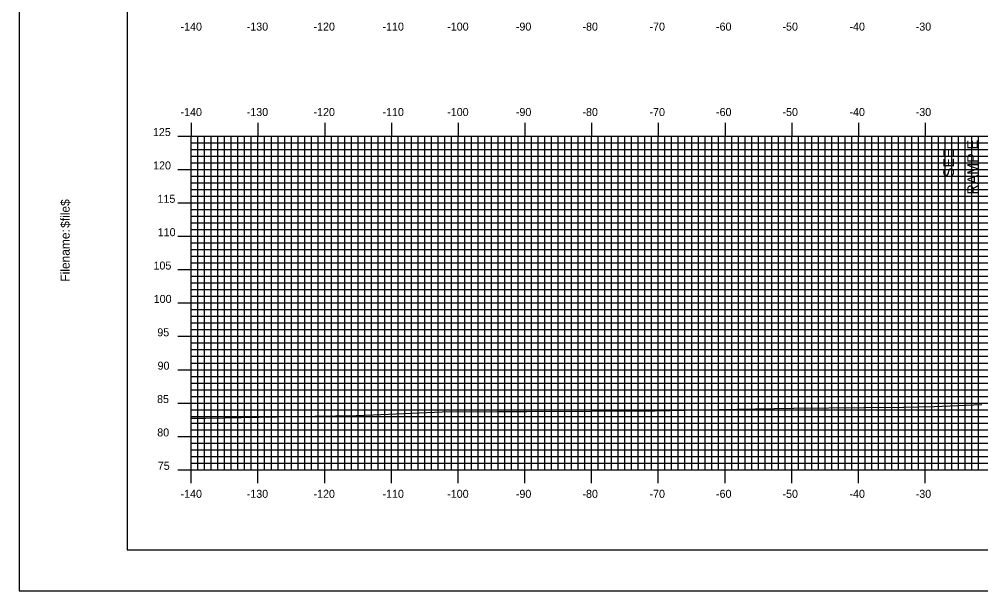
# Model space of a CAD drawing. Extents: x 92 to 435, y -1658 to -1438.
# Drawn here: x 91.8 to 236, y -1657.7 to -1572.1 of the extents above; entities that cross this region are included whole.
import ezdxf

# ---------------------------------------------------------------- set-up
doc = ezdxf.new("R2010")
doc.units = 0
for name, color, linetype in [('ANNOTATION', 7, 'Continuous'), ('BORDER', 7, 'Continuous'), ('H_V ANNOTATION', 7, 'Continuous'), ('MAJOR', 7, 'Continuous'), ('MINOR', 7, 'Continuous'), ('PLOT BOUNDARY', 7, 'Continuous'), ('S_Roadway_Centerline', 7, 'Continuous')]:
    doc.layers.add(name, color=color, linetype=linetype)

msp = doc.modelspace()

# ---------------------------------------------------------------- linework, layer by layer
at = {"layer": 'BORDER'}
msp.add_lwpolyline([(108.02, -1651.6), (428.02, -1651.6), (428.02, -1441.6), (108.02, -1441.6)], close=True, dxfattribs=at)
at = {"layer": 'MAJOR'}
for p, q in [((117.62, -1587.6), (117.62, -1589.6)), ((127.62, -1587.6), (127.62, -1589.6)), ((137.62, -1587.6), (137.62, -1589.6)), ((147.62, -1587.6), (147.62, -1589.6)), ((157.62, -1587.6), (157.62, -1589.6)), ((167.62, -1587.6), (167.62, -1589.6)), ((177.62, -1587.6), (177.62, -1589.6)), ((187.62, -1587.6), (187.62, -1589.6)), ((197.62, -1587.6), (197.62, -1589.6)), ((207.62, -1587.6), (207.62, -1589.6)), ((217.62, -1587.6), (217.62, -1589.6)), ((227.62, -1587.6), (227.62, -1589.6)), ((115.62, -1589.6), (117.62, -1589.6)), ((117.62, -1589.6), (397.62, -1589.6)), ((117.62, -1639.6), (117.62, -1589.6)), ((117.62, -1639.6), (117.62, -1589.6)), ((117.62, -1589.6), (397.62, -1589.6)), ((127.62, -1639.6), (127.62, -1589.6)), ((137.62, -1639.6), (137.62, -1589.6)), ((147.62, -1639.6), (147.62, -1589.6)), ((157.62, -1639.6), (157.62, -1589.6)), ((167.62, -1639.6), (167.62, -1589.6)), ((177.62, -1639.6), (177.62, -1589.6)), ((187.62, -1639.6), (187.62, -1589.6)), ((197.62, -1639.6), (197.62, -1589.6)), ((207.62, -1639.6), (207.62, -1589.6)), ((217.62, -1639.6), (217.62, -1589.6)), ((227.62, -1639.6), (227.62, -1589.6)), ((115.62, -1594.6), (117.62, -1594.6)), ((117.62, -1594.6), (397.62, -1594.6)), ((115.62, -1599.6), (117.62, -1599.6)), ((117.62, -1599.6), (397.62, -1599.6)), ((115.62, -1604.6), (117.62, -1604.6)), ((117.62, -1604.6), (397.62, -1604.6)), ((115.62, -1609.6), (117.62, -1609.6)), ((117.62, -1609.6), (397.62, -1609.6)), ((115.62, -1614.6), (117.62, -1614.6)), ((117.62, -1614.6), (397.62, -1614.6)), ((115.62, -1619.6), (117.62, -1619.6)), ((117.62, -1619.6), (397.62, -1619.6)), ((115.62, -1624.6), (117.62, -1624.6)), ((117.62, -1624.6), (397.62, -1624.6)), ((115.62, -1629.6), (117.62, -1629.6)), ((117.62, -1629.6), (397.62, -1629.6)), ((115.62, -1634.6), (117.62, -1634.6)), ((117.62, -1634.6), (397.62, -1634.6)), ((115.62, -1639.6), (117.62, -1639.6)), ((117.62, -1639.6), (397.62, -1639.6)), ((117.62, -1639.6), (397.62, -1639.6)), ((117.62, -1641.61), (117.62, -1639.6)), ((127.62, -1641.61), (127.62, -1639.6)), ((137.62, -1641.61), (137.62, -1639.6)), ((147.62, -1641.61), (147.62, -1639.6)), ((157.62, -1641.61), (157.62, -1639.6)), ((167.62, -1641.61), (167.62, -1639.6)), ((177.62, -1641.61), (177.62, -1639.6)), ((187.62, -1641.61), (187.62, -1639.6)), ((197.62, -1641.61), (197.62, -1639.6)), ((207.62, -1641.61), (207.62, -1639.6)), ((217.62, -1641.61), (217.62, -1639.6)), ((227.62, -1641.61), (227.62, -1639.6))]:
    msp.add_line(p, q, dxfattribs=at)
at = {"layer": 'MINOR'}
for p, q in [((117.62, -1590.6), (397.62, -1590.6)), ((117.62, -1590.6), (119.63, -1590.6)), ((118.62, -1639.6), (118.62, -1589.6)), ((119.62, -1639.6), (119.62, -1589.6)), ((120.62, -1639.6), (120.62, -1589.6)), ((121.62, -1639.6), (121.62, -1589.6)), ((122.62, -1639.6), (122.62, -1589.6)), ((123.62, -1639.6), (123.62, -1589.6)), ((124.62, -1639.6), (124.62, -1589.6)), ((125.62, -1639.6), (125.62, -1589.6)), ((126.62, -1639.6), (126.62, -1589.6)), ((128.62, -1639.6), (128.62, -1589.6)), ((129.62, -1639.6), (129.62, -1589.6)), ((130.62, -1639.6), (130.62, -1589.6)), ((131.62, -1639.6), (131.62, -1589.6)), ((132.62, -1639.6), (132.62, -1589.6)), ((133.62, -1639.6), (133.62, -1589.6)), ((134.62, -1639.6), (134.62, -1589.6)), ((135.62, -1639.6), (135.62, -1589.6)), ((136.62, -1639.6), (136.62, -1589.6)), ((138.62, -1639.6), (138.62, -1589.6)), ((139.62, -1639.6), (139.62, -1589.6)), ((140.62, -1639.6), (140.62, -1589.6)), ((141.62, -1639.6), (141.62, -1589.6)), ((142.62, -1639.6), (142.62, -1589.6)), ((143.62, -1639.6), (143.62, -1589.6)), ((144.62, -1639.6), (144.62, -1589.6)), ((145.62, -1639.6), (145.62, -1589.6)), ((146.62, -1639.6), (146.62, -1589.6)), ((148.62, -1639.6), (148.62, -1589.6)), ((149.62, -1639.6), (149.62, -1589.6)), ((150.62, -1639.6), (150.62, -1589.6)), ((151.62, -1639.6), (151.62, -1589.6)), ((152.62, -1639.6), (152.62, -1589.6)), ((153.62, -1639.6), (153.62, -1589.6)), ((154.62, -1639.6), (154.62, -1589.6)), ((155.62, -1639.6), (155.62, -1589.6)), ((156.62, -1639.6), (156.62, -1589.6)), ((158.62, -1639.6), (158.62, -1589.6)), ((159.62, -1639.6), (159.62, -1589.6)), ((160.62, -1639.6), (160.62, -1589.6)), ((161.62, -1639.6), (161.62, -1589.6)), ((162.62, -1639.6), (162.62, -1589.6)), ((163.62, -1639.6), (163.62, -1589.6)), ((164.62, -1639.6), (164.62, -1589.6)), ((165.62, -1639.6), (165.62, -1589.6)), ((166.62, -1639.6), (166.62, -1589.6)), ((168.62, -1639.6), (168.62, -1589.6)), ((169.62, -1639.6), (169.62, -1589.6)), ((170.62, -1639.6), (170.62, -1589.6)), ((171.62, -1639.6), (171.62, -1589.6)), ((172.62, -1639.6), (172.62, -1589.6)), ((173.62, -1639.6), (173.62, -1589.6)), ((174.62, -1639.6), (174.62, -1589.6)), ((175.62, -1639.6), (175.62, -1589.6)), ((176.62, -1639.6), (176.62, -1589.6)), ((178.62, -1639.6), (178.62, -1589.6)), ((179.62, -1639.6), (179.62, -1589.6)), ((180.62, -1639.6), (180.62, -1589.6)), ((181.62, -1639.6), (181.62, -1589.6)), ((182.62, -1639.6), (182.62, -1589.6)), ((183.62, -1639.6), (183.62, -1589.6)), ((184.62, -1639.6), (184.62, -1589.6)), ((185.62, -1639.6), (185.62, -1589.6)), ((186.62, -1639.6), (186.62, -1589.6)), ((188.62, -1639.6), (188.62, -1589.6)), ((189.62, -1639.6), (189.62, -1589.6)), ((190.62, -1639.6), (190.62, -1589.6)), ((191.62, -1639.6), (191.62, -1589.6)), ((192.62, -1639.6), (192.62, -1589.6)), ((193.62, -1639.6), (193.62, -1589.6)), ((194.62, -1639.6), (194.62, -1589.6)), ((195.62, -1639.6), (195.62, -1589.6)), ((196.62, -1639.6), (196.62, -1589.6)), ((198.62, -1639.6), (198.62, -1589.6)), ((199.62, -1639.6), (199.62, -1589.6)), ((200.62, -1639.6), (200.62, -1589.6)), ((201.62, -1639.6), (201.62, -1589.6)), ((202.62, -1639.6), (202.62, -1589.6)), ((203.62, -1639.6), (203.62, -1589.6)), ((204.62, -1639.6), (204.62, -1589.6)), ((205.62, -1639.6), (205.62, -1589.6)), ((206.62, -1639.6), (206.62, -1589.6)), ((208.62, -1639.6), (208.62, -1589.6)), ((209.62, -1639.6), (209.62, -1589.6)), ((210.62, -1639.6), (210.62, -1589.6)), ((211.62, -1639.6), (211.62, -1589.6)), ((212.62, -1639.6), (212.62, -1589.6)), ((213.62, -1639.6), (213.62, -1589.6)), ((214.62, -1639.6), (214.62, -1589.6)), ((215.62, -1639.6), (215.62, -1589.6)), ((216.62, -1639.6), (216.62, -1589.6)), ((218.62, -1639.6), (218.62, -1589.6)), ((219.62, -1639.6), (219.62, -1589.6)), ((220.62, -1639.6), (220.62, -1589.6)), ((221.62, -1639.6), (221.62, -1589.6)), ((222.62, -1639.6), (222.62, -1589.6)), ((223.62, -1639.6), (223.62, -1589.6)), ((224.62, -1639.6), (224.62, -1589.6)), ((225.62, -1639.6), (225.62, -1589.6)), ((226.62, -1639.6), (226.62, -1589.6)), ((228.62, -1639.6), (228.62, -1589.6)), ((229.62, -1639.6), (229.62, -1589.6)), ((230.62, -1639.6), (230.62, -1589.6)), ((231.62, -1639.6), (231.62, -1589.6)), ((232.62, -1639.6), (232.62, -1589.6)), ((233.62, -1639.6), (233.62, -1589.6)), ((234.62, -1639.6), (234.62, -1589.6)), ((235.62, -1639.6), (235.62, -1589.6)), ((117.62, -1591.6), (397.62, -1591.6)), ((117.62, -1591.6), (119.63, -1591.6)), ((117.62, -1592.6), (397.62, -1592.6)), ((117.62, -1592.6), (119.63, -1592.6)), ((117.62, -1593.6), (397.62, -1593.6)), ((117.62, -1593.6), (119.63, -1593.6)), ((117.62, -1595.6), (397.62, -1595.6)), ((117.62, -1595.6), (119.63, -1595.6)), ((117.62, -1596.6), (397.62, -1596.6)), ((117.62, -1596.6), (119.63, -1596.6)), ((117.62, -1597.6), (397.62, -1597.6)), ((117.62, -1597.6), (119.63, -1597.6)), ((117.62, -1598.6), (397.62, -1598.6)), ((117.62, -1598.6), (119.63, -1598.6)), ((117.62, -1600.6), (397.62, -1600.6)), ((117.62, -1600.6), (119.63, -1600.6)), ((117.62, -1601.6), (397.62, -1601.6)), ((117.62, -1601.6), (119.63, -1601.6)), ((117.62, -1602.6), (397.62, -1602.6)), ((117.62, -1602.6), (119.63, -1602.6)), ((117.62, -1603.6), (397.62, -1603.6)), ((117.62, -1603.6), (119.63, -1603.6)), ((117.62, -1605.6), (397.62, -1605.6)), ((117.62, -1605.6), (119.63, -1605.6)), ((117.62, -1606.6), (397.62, -1606.6)), ((117.62, -1606.6), (119.63, -1606.6)), ((117.62, -1607.6), (397.62, -1607.6)), ((117.62, -1607.6), (119.63, -1607.6)), ((117.62, -1608.6), (397.62, -1608.6)), ((117.62, -1608.6), (119.63, -1608.6)), ((117.62, -1610.6), (397.62, -1610.6)), ((117.62, -1610.6), (119.63, -1610.6)), ((117.62, -1611.6), (397.62, -1611.6)), ((117.62, -1611.6), (119.63, -1611.6)), ((117.62, -1612.6), (397.62, -1612.6)), ((117.62, -1612.6), (119.63, -1612.6)), ((117.62, -1613.6), (397.62, -1613.6)), ((117.62, -1613.6), (119.63, -1613.6)), ((117.62, -1615.6), (397.62, -1615.6)), ((117.62, -1615.6), (119.63, -1615.6)), ((117.62, -1616.6), (397.62, -1616.6)), ((117.62, -1616.6), (119.63, -1616.6)), ((117.62, -1617.6), (397.62, -1617.6)), ((117.62, -1617.6), (119.63, -1617.6)), ((117.62, -1618.6), (397.62, -1618.6)), ((117.62, -1618.6), (119.63, -1618.6)), ((117.62, -1620.6), (397.62, -1620.6)), ((117.62, -1620.6), (119.63, -1620.6)), ((117.62, -1621.6), (397.62, -1621.6)), ((117.62, -1621.6), (119.63, -1621.6)), ((117.62, -1622.6), (397.62, -1622.6)), ((117.62, -1622.6), (119.63, -1622.6)), ((117.62, -1623.6), (397.62, -1623.6)), ((117.62, -1623.6), (119.63, -1623.6)), ((117.62, -1625.6), (397.62, -1625.6)), ((117.62, -1625.6), (119.63, -1625.6)), ((117.62, -1626.6), (397.62, -1626.6)), ((117.62, -1626.6), (119.63, -1626.6)), ((117.62, -1627.6), (397.62, -1627.6)), ((117.62, -1627.6), (119.63, -1627.6)), ((117.62, -1628.6), (397.62, -1628.6)), ((117.62, -1628.6), (119.63, -1628.6)), ((117.62, -1630.6), (397.62, -1630.6)), ((117.62, -1630.6), (119.63, -1630.6)), ((117.62, -1631.6), (397.62, -1631.6)), ((117.62, -1631.6), (119.63, -1631.6)), ((117.62, -1632.6), (397.62, -1632.6)), ((117.62, -1632.6), (119.63, -1632.6)), ((117.62, -1633.6), (397.62, -1633.6)), ((117.62, -1633.6), (119.63, -1633.6)), ((117.62, -1635.6), (397.62, -1635.6)), ((117.62, -1635.6), (119.63, -1635.6)), ((117.62, -1636.6), (397.62, -1636.6)), ((117.62, -1636.6), (119.63, -1636.6)), ((117.62, -1637.6), (397.62, -1637.6)), ((117.62, -1637.6), (119.63, -1637.6)), ((117.62, -1638.6), (397.62, -1638.6)), ((117.62, -1638.6), (119.63, -1638.6))]:
    msp.add_line(p, q, dxfattribs=at)
at = {"layer": 'PLOT BOUNDARY'}
msp.add_lwpolyline([(91.83, -1657.72), (431.83, -1657.72), (431.83, -1437.72), (91.83, -1437.72)], close=True, dxfattribs=at)
at = {"layer": 'S_Roadway_Centerline'}
msp.add_lwpolyline([(117.62, -1631.84), (119.74, -1631.85), (122.52, -1631.81), (133.02, -1631.63), (142.34, -1631.46), (144.88, -1631.37), (155.2, -1630.94), (163.68, -1630.89), (167.91, -1630.85), (187.14, -1630.76), (193.67, -1630.62), (207.87, -1630.36), (218.41, -1630.29), (224.43, -1630.23), (228.97, -1630.12), (236.13, -1629.82)], dxfattribs=at)

# ---------------------------------------------------------------- texts
at = {"layer": 'ANNOTATION'}
for s, p in [('RAMP E', (235.53, -1598.37)), ('SEE', (231.93, -1595.75))]:
    msp.add_text(s, height=1.6, rotation=90, dxfattribs=at).set_placement(p)
at = {"layer": 'BORDER'}
for s, p in [('$file$', (99.39, -1603.35)), ('Filename:', (99.39, -1611.41))]:
    msp.add_text(s, height=1.339, rotation=90, dxfattribs=at).set_placement(p)
at = {"layer": 'H_V ANNOTATION'}
for s, p in [('-140', (116.01, -1573.8)), ('-130', (125.93, -1573.8)), ('-120', (135.94, -1573.8)), ('-110', (146.28, -1573.8)), ('-100', (155.98, -1573.8)), ('-90', (166.27, -1573.8)), ('-80', (176.25, -1573.8)), ('-70', (186.3, -1573.8)), ('-60', (196.27, -1573.8)), ('-50', (206.23, -1573.8)), ('-40', (216.27, -1573.8)), ('-30', (226.2, -1573.8)), ('-140', (116.01, -1586.6)), ('-130', (125.93, -1586.6)), ('-120', (135.94, -1586.6)), ('-110', (146.28, -1586.6)), ('-100', (155.98, -1586.6)), ('-90', (166.27, -1586.6)), ('-80', (176.25, -1586.6)), ('-70', (186.3, -1586.6)), ('-60', (196.27, -1586.6)), ('-50', (206.23, -1586.6)), ('-40', (216.27, -1586.6)), ('-30', (226.2, -1586.6)), ('125', (111.87, -1589.6)), ('120', (111.9, -1594.6)), ('115', (112.56, -1599.6)), ('110', (112.59, -1604.6)), ('105', (111.96, -1609.6)), ('100', (111.99, -1614.6)), ('95', (112.53, -1619.6)), ('90', (112.57, -1624.6)), ('85', (112.49, -1629.6)), ('80', (112.52, -1634.6)), ('75', (112.6, -1639.6)), ('-140', (116.01, -1643.8)), ('-130', (125.93, -1643.8)), ('-120', (135.94, -1643.8)), ('-110', (146.28, -1643.8)), ('-100', (155.98, -1643.8)), ('-90', (166.27, -1643.8)), ('-80', (176.25, -1643.8)), ('-70', (186.3, -1643.8)), ('-60', (196.27, -1643.8)), ('-50', (206.23, -1643.8)), ('-40', (216.27, -1643.8)), ('-30', (226.2, -1643.8))]:
    msp.add_text(s, height=1.2, dxfattribs=at).set_placement(p)
at = {"layer": 'MAJOR'}
msp.add_text('-', height=0.012, dxfattribs=at).set_placement((117.61, -1639.6))

doc.saveas('drawing.dxf')
